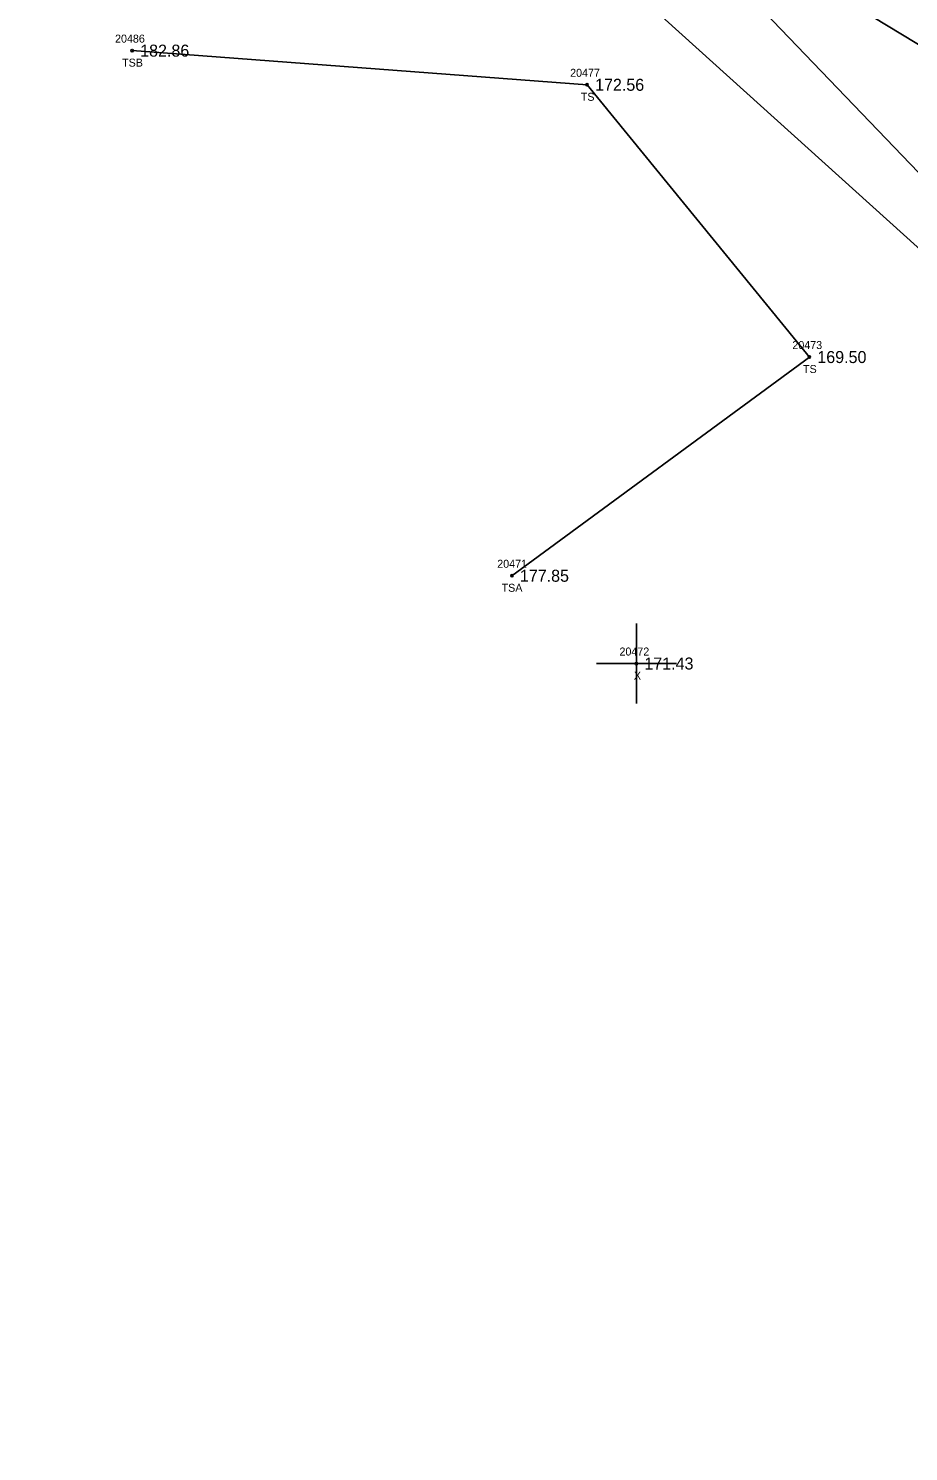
# Model space of a CAD drawing. Extents: x 2279528 to 2280976, y 1061373 to 1062235.
# Drawn here: x 2279975.6 to 2280085.6, y 1061818 to 1061995.9 of the extents above; entities that cross this region are included whole.
import ezdxf

# ---------------------------------------------------------------- set-up
doc = ezdxf.new("R2010")
doc.units = 0
for name, color, linetype in [('RD_DTM_BkLn2', 7, 'Continuous'), ('RD_DTM_BkLn_txCode', 7, 'Continuous'), ('RD_EX_H2O', 7, 'Continuous'), ('RD_EX_Misc', 7, 'Continuous'), ('RD_EX_Misc_txCode', 7, 'Continuous'), ('RD_EX_TX_Misc_ELEV', 7, 'Continuous'), ('RD_SMD_Locator', 7, 'Continuous')]:
    doc.layers.add(name, color=color, linetype=linetype)

msp = doc.modelspace()

# ---------------------------------------------------------------- linework, layer by layer
at = {"layer": 'RD_DTM_BkLn2'}
msp.add_lwpolyline([(2280036.07, 1061927.47), (2280073.25, 1061954.81), (2280045.47, 1061988.84), (2279988.61, 1061993.11)], dxfattribs=at)
at = {"layer": 'RD_EX_H2O'}
for points in [[(2280211.16, 1061800.79), (2280200.18, 1061802.95), (2280195.55, 1061801.16), (2280185.62, 1061809.36), (2280166.4, 1061839.27), (2280165.19, 1061847.77), (2280176.13, 1061895.97), (2280173.38, 1061913.11), (2280146.96, 1061940.88), (2280090.97, 1061964.76), (2280049.27, 1062002.4), (2280058.65, 1062048.88), (2280050.78, 1062064.28), (2280035.9, 1062083.09), (2280001.73, 1062095.49), (2279975.65, 1062129.45), (2279976.82, 1062173.44)], [(2280168.33, 1061843.42), (2280183.83, 1061895.62), (2280179.4, 1061916.69), (2280147.37, 1061943.73), (2280094.98, 1061969.47), (2280057.58, 1062008.45), (2280067.95, 1062052.6), (2280055.34, 1062070.59), (2280037.3, 1062087.39), (2280003.55, 1062098.15), (2279979.87, 1062130.72), (2279980.65, 1062169.39)], [(2280245.52, 1061819.46), (2280233.94, 1061826.17), (2280221.09, 1061822.97), (2280184.1, 1061845.49), (2280188.88, 1061876.01), (2280197.41, 1061894.2), (2280195.18, 1061912.5), (2280158.13, 1061956.7), (2280101.97, 1061984.74), (2280076.14, 1062000.42), (2280073.45, 1062020.04), (2280088.34, 1062054.57), (2280063.06, 1062089.79), (2280022.01, 1062117.09), (2280004.42, 1062121.87), (2279996.3, 1062161.48)]]:
    msp.add_lwpolyline(points, dxfattribs=at)
at = {"layer": 'RD_EX_Misc'}
for p, q in [((2280051.63, 1061911.5), (2280051.63, 1061921.5)), ((2280046.63, 1061916.5), (2280056.63, 1061916.5))]:
    msp.add_line(p, q, dxfattribs=at)
at = {"layer": 'RD_SMD_Locator'}
for centre in [(2279988.61, 1061993.11), (2280045.47, 1061988.84), (2280073.25, 1061954.81), (2280036.07, 1061927.47), (2280051.63, 1061916.5)]:
    msp.add_circle(centre, 0.15, dxfattribs=at)

# ---------------------------------------------------------------- texts
at = {"layer": 'RD_DTM_BkLn_txCode'}
for s, p in [('20486', (2279986.47, 1061994.11)), ('TSB', (2279987.35, 1061991.11)), ('20477', (2280043.35, 1061989.84)), ('TS', (2280044.68, 1061986.84)), ('20473', (2280071.13, 1061955.81)), ('TS', (2280072.46, 1061952.81)), ('20471', (2280034.24, 1061928.47)), ('TSA', (2280034.79, 1061925.47))]:
    msp.add_text(s, height=1, dxfattribs=at).set_placement(p)
at = {"layer": 'RD_EX_Misc_txCode'}
for s, p in [('20472', (2280049.52, 1061917.5)), ('X', (2280051.32, 1061914.5))]:
    msp.add_text(s, height=1, dxfattribs=at).set_placement(p)
at = {"layer": 'RD_EX_TX_Misc_ELEV'}
for s, p in [('182.86', (2279989.61, 1061992.36)), ('172.56', (2280046.47, 1061988.09)), ('169.50', (2280074.25, 1061954.06)), ('177.85', (2280037.07, 1061926.72)), ('171.43', (2280052.63, 1061915.75))]:
    msp.add_text(s, height=1.5, dxfattribs=at).set_placement(p)

doc.saveas('drawing.dxf')
